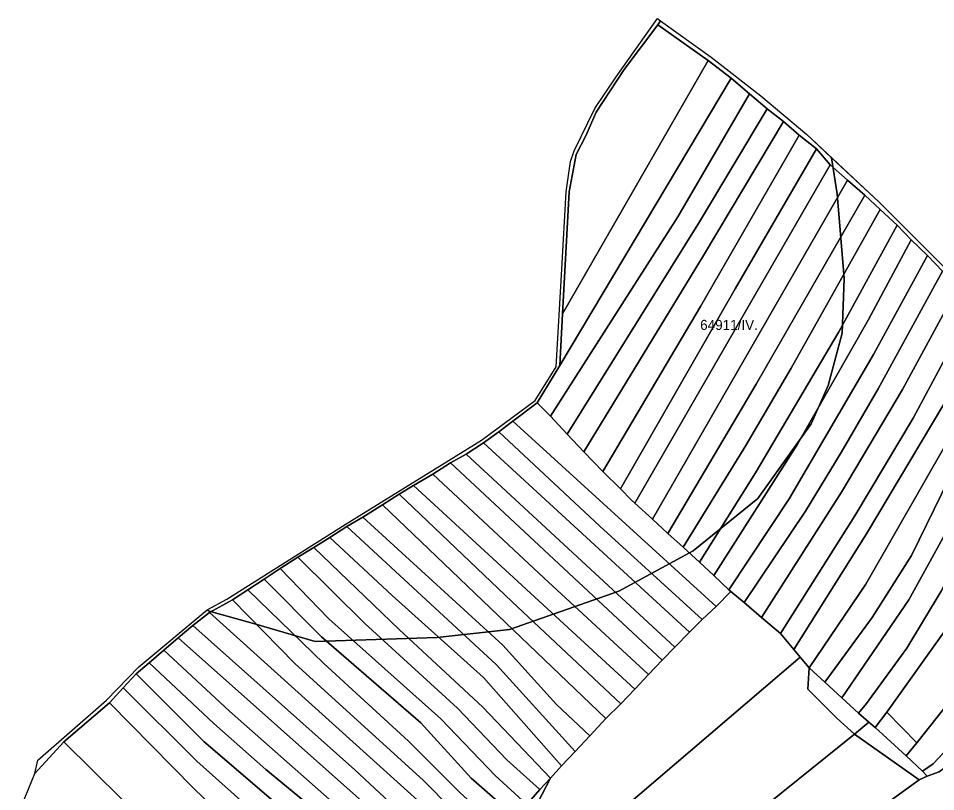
# Model space of a CAD drawing. Extents: x -521261 to -517465, y -1182764 to -1179456.
# Drawn here: x -519678.3 to -519223.1, y -1179839.4 to -1179455.9 of the extents above; entities that cross this region are included whole.
import ezdxf

# ---------------------------------------------------------------- set-up
doc = ezdxf.new("R2010")
doc.units = 0
for name, color, linetype in [('95560013', 7, 'Continuous'), ('95610013', 7, 'Continuous'), ('95620013', 7, 'Continuous'), ('95640013', 7, 'Continuous'), ('95660013', 7, 'Continuous')]:
    doc.layers.add(name, color=color, linetype=linetype)

msp = doc.modelspace()

# ---------------------------------------------------------------- linework, layer by layer
at = {"layer": '95560013'}
for points in [[(-519361.03, -1179459.21), (-519335.99, -1179476.93), (-519408.24, -1179602.42), (-519404.91, -1179542.03), (-519401.48, -1179523.46), (-519396.76, -1179514.25), (-519391.52, -1179502.49), (-519377.6, -1179481.27)], [(-519335.99, -1179476.93), (-519324.66, -1179485.69), (-519409.54, -1179628.05), (-519408.24, -1179602.42)], [(-519324.66, -1179485.69), (-519315.41, -1179493.46), (-519351.01, -1179554.42), (-519414.24, -1179653.26), (-519420.84, -1179646.66), (-519409.54, -1179628.05)], [(-519315.41, -1179493.46), (-519306.64, -1179500.75), (-519340.21, -1179556.81), (-519405.88, -1179662.23), (-519414.24, -1179653.26), (-519351.01, -1179554.42)], [(-519306.64, -1179500.75), (-519298.66, -1179507.18), (-519338.3, -1179573.5), (-519397.74, -1179670.84), (-519405.88, -1179662.23), (-519340.21, -1179556.81)], [(-519298.66, -1179507.18), (-519290.83, -1179513.92), (-519339.86, -1179598.77), (-519388.2, -1179680.61), (-519397.74, -1179670.84), (-519338.3, -1179573.5)], [(-519290.83, -1179513.92), (-519282.3, -1179520.6), (-519322.59, -1179590.16), (-519379.43, -1179689.33), (-519388.2, -1179680.61), (-519339.86, -1179598.77)], [(-519282.3, -1179520.6), (-519275.39, -1179528.63), (-519372.33, -1179696.43), (-519374.03, -1179694.94), (-519379.43, -1179689.33), (-519322.59, -1179590.16)], [(-519275.39, -1179528.63), (-519266.89, -1179536.14), (-519318.19, -1179625.29), (-519363.61, -1179704.38), (-519372.33, -1179696.43)], [(-519266.89, -1179536.14), (-519258.26, -1179543.63), (-519312.18, -1179637.33), (-519356.03, -1179711.44), (-519363.61, -1179704.38), (-519318.19, -1179625.29)], [(-519258.26, -1179543.63), (-519250.63, -1179550.72), (-519294.75, -1179629.37), (-519317.27, -1179667.84), (-519348.37, -1179718.13), (-519356.03, -1179711.44), (-519312.18, -1179637.33)], [(-519250.63, -1179550.72), (-519242.26, -1179558.54), (-519271.17, -1179611.41), (-519312.48, -1179681.33), (-519340.31, -1179725.57), (-519348.37, -1179718.13), (-519317.27, -1179667.84), (-519294.75, -1179629.37)], [(-519242.26, -1179558.54), (-519235.24, -1179565.85), (-519256.56, -1179605.64), (-519291.61, -1179667.15), (-519333.12, -1179732.17), (-519340.31, -1179725.57), (-519312.48, -1179681.33), (-519271.17, -1179611.41)], [(-519235.24, -1179565.85), (-519227.21, -1179573.63), (-519253.98, -1179622.58), (-519295.83, -1179694.23), (-519325.66, -1179739.27), (-519333.12, -1179732.17), (-519291.61, -1179667.15), (-519256.56, -1179605.64)], [(-519227.21, -1179573.63), (-519219.73, -1179581.26), (-519251.57, -1179639.65), (-519270, -1179671.32), (-519287.7, -1179700.28), (-519318.17, -1179745.69), (-519324.74, -1179740.24), (-519325.66, -1179739.27), (-519295.83, -1179694.23), (-519253.98, -1179622.58)], [(-519219.73, -1179581.26), (-519212.15, -1179589.49), (-519239.59, -1179639.98), (-519269.79, -1179690.95), (-519309.58, -1179753.02), (-519318.17, -1179745.69), (-519287.7, -1179700.28), (-519270, -1179671.32), (-519251.57, -1179639.65)], [(-519212.15, -1179589.49), (-519204.52, -1179598.75), (-519234.32, -1179654.26), (-519263.2, -1179702.59), (-519300.17, -1179761.03), (-519309.58, -1179753.02), (-519269.79, -1179690.95), (-519239.59, -1179639.98)], [(-519201.94, -1179601.66), (-519198.05, -1179606.76), (-519219.06, -1179647.31), (-519257.37, -1179711.63), (-519293.42, -1179768.94), (-519300.17, -1179761.03), (-519263.2, -1179702.59), (-519234.32, -1179654.26), (-519204.52, -1179598.75)], [(-519198.05, -1179606.76), (-519192.16, -1179610.6), (-519218.52, -1179663.34), (-519216.58, -1179664.63), (-519257.8, -1179736.51), (-519285.96, -1179778.08), (-519290.27, -1179772.81), (-519293.42, -1179768.94), (-519257.37, -1179711.63), (-519219.06, -1179647.31)], [(-519414.24, -1179653.26), (-519405.88, -1179662.23), (-519397.74, -1179670.84), (-519388.2, -1179680.61), (-519379.43, -1179689.33), (-519374.03, -1179694.94), (-519372.33, -1179696.43), (-519363.61, -1179704.38), (-519356.03, -1179711.44), (-519348.37, -1179718.13), (-519340.31, -1179725.57), (-519333.12, -1179732.17), (-519325.66, -1179739.27), (-519324.74, -1179740.24), (-519331.97, -1179747.61), (-519432.94, -1179655.75), (-519420.84, -1179646.66)], [(-519439.84, -1179660.98), (-519432.94, -1179655.75), (-519331.97, -1179747.61), (-519338.93, -1179754.09), (-519389.67, -1179707.71)], [(-519447.42, -1179666.48), (-519439.84, -1179660.98), (-519389.67, -1179707.71), (-519338.93, -1179754.09), (-519345.21, -1179760.33)], [(-519208.94, -1179668.99), (-519235.04, -1179722.32), (-519254.59, -1179753.09), (-519278.09, -1179785.19), (-519285.96, -1179778.08), (-519257.8, -1179736.51), (-519216.58, -1179664.63)], [(-519456.09, -1179672.01), (-519447.42, -1179666.48), (-519345.21, -1179760.33), (-519352.56, -1179767.71)], [(-519200.9, -1179673.95), (-519219.5, -1179713.79), (-519236.39, -1179744.27), (-519269.7, -1179792.92), (-519278.09, -1179785.19), (-519254.59, -1179753.09), (-519235.04, -1179722.32), (-519208.94, -1179668.99)], [(-519463.87, -1179676.33), (-519456.09, -1179672.01), (-519352.56, -1179767.71), (-519358.76, -1179774.28)], [(-519192.45, -1179678.83), (-519208.08, -1179716.23), (-519220.4, -1179740.02), (-519237.39, -1179768.34), (-519257.44, -1179795.7), (-519261.34, -1179800.45), (-519269.7, -1179792.92), (-519236.39, -1179744.27), (-519219.5, -1179713.79), (-519200.9, -1179673.95)], [(-519472.58, -1179681.98), (-519463.87, -1179676.33), (-519358.76, -1179774.28), (-519365.58, -1179781.36), (-519417.45, -1179733.41)], [(-519482.18, -1179687.66), (-519472.58, -1179681.98), (-519417.45, -1179733.41), (-519365.58, -1179781.36), (-519372.32, -1179788.53)], [(-519489.37, -1179691.96), (-519482.18, -1179687.66), (-519372.32, -1179788.53), (-519379.3, -1179795.8), (-519433.17, -1179745.31)], [(-519497.64, -1179697.24), (-519489.37, -1179691.96), (-519433.17, -1179745.31), (-519379.3, -1179795.8), (-519386.79, -1179803.12)], [(-519507.31, -1179703.34), (-519497.64, -1179697.24), (-519386.79, -1179803.12), (-519394.73, -1179811.81), (-519411.23, -1179796.2), (-519437.91, -1179766.86)], [(-519515.2, -1179707.94), (-519507.31, -1179703.34), (-519437.91, -1179766.86), (-519411.23, -1179796.2), (-519394.73, -1179811.81), (-519401.97, -1179819.49), (-519441.01, -1179776.5)], [(-519523.71, -1179713.36), (-519515.2, -1179707.94), (-519441.01, -1179776.5), (-519401.97, -1179819.49), (-519408.69, -1179826.66), (-519447.53, -1179782.85), (-519492.73, -1179742.1)], [(-519531.57, -1179718.35), (-519523.71, -1179713.36), (-519492.73, -1179742.1), (-519447.53, -1179782.85), (-519408.69, -1179826.66), (-519414.29, -1179832.69), (-519447.72, -1179797.47), (-519489.38, -1179758.96)], [(-519539.55, -1179723.19), (-519531.57, -1179718.35), (-519489.38, -1179758.96), (-519447.72, -1179797.47), (-519414.29, -1179832.69), (-519419.43, -1179838.35), (-519435.84, -1179823.64), (-519460.43, -1179797.99), (-519506.36, -1179756.12)], [(-519548.4, -1179728.82), (-519539.55, -1179723.19), (-519506.36, -1179756.12), (-519460.43, -1179797.99), (-519435.84, -1179823.64), (-519419.43, -1179838.35), (-519423.83, -1179843.37), (-519425.9, -1179845.77), (-519441.61, -1179831.42), (-519468.61, -1179803.29), (-519524.14, -1179753.78)], [(-519556.27, -1179734.13), (-519548.4, -1179728.82), (-519524.14, -1179753.78), (-519468.61, -1179803.29), (-519441.61, -1179831.42), (-519425.9, -1179845.77), (-519431.26, -1179852.28), (-519453.56, -1179832.73), (-519478.58, -1179805.33), (-519527.89, -1179762.65)], [(-519564.43, -1179739.4), (-519556.27, -1179734.13), (-519527.89, -1179762.65), (-519478.58, -1179805.33), (-519453.56, -1179832.73), (-519431.26, -1179852.28), (-519437.26, -1179859.88), (-519459.17, -1179839.89), (-519484.71, -1179814.34), (-519526.65, -1179775.84)], [(-519572.01, -1179744.28), (-519564.43, -1179739.4), (-519526.65, -1179775.84), (-519484.71, -1179814.34), (-519459.17, -1179839.89), (-519437.26, -1179859.88), (-519442.74, -1179866.13), (-519463.3, -1179847.89), (-519477.15, -1179833.93), (-519541.13, -1179775.85)], [(-519324.74, -1179740.24), (-519318.17, -1179745.69), (-519309.58, -1179753.02), (-519300.17, -1179761.03), (-519293.42, -1179768.94), (-519290.27, -1179772.81), (-519405.1, -1179870.79), (-519441.45, -1179905.77), (-519434.67, -1179872.01), (-519414.29, -1179832.69), (-519408.69, -1179826.66), (-519401.97, -1179819.49), (-519394.73, -1179811.81), (-519386.79, -1179803.12), (-519379.3, -1179795.8), (-519372.32, -1179788.53), (-519365.58, -1179781.36), (-519358.76, -1179774.28), (-519352.56, -1179767.71), (-519345.21, -1179760.33), (-519338.93, -1179754.09), (-519331.97, -1179747.61)], [(-519583.34, -1179750.61), (-519572.01, -1179744.28), (-519541.13, -1179775.85), (-519477.15, -1179833.93), (-519463.3, -1179847.89), (-519442.74, -1179866.13), (-519447.98, -1179872.79)], [(-519591.65, -1179757.1), (-519583.34, -1179750.61), (-519447.98, -1179872.79), (-519453.81, -1179880.12), (-519477.04, -1179860.53), (-519511.27, -1179828.64)], [(-519598.98, -1179763.08), (-519591.65, -1179757.1), (-519511.27, -1179828.64), (-519477.04, -1179860.53), (-519453.81, -1179880.12), (-519459.24, -1179886.88), (-519484.38, -1179866.3), (-519500.43, -1179850.73)], [(-519606.08, -1179769.24), (-519598.98, -1179763.08), (-519500.43, -1179850.73), (-519484.38, -1179866.3), (-519497.57, -1179856.71), (-519505.44, -1179859.57), (-519573.52, -1179799.52)], [(-519613.36, -1179775.48), (-519606.08, -1179769.24), (-519573.52, -1179799.52), (-519505.44, -1179859.57), (-519514.27, -1179862.4), (-519555.48, -1179828.46), (-519581.24, -1179805.68)], [(-519285.96, -1179778.08), (-519286.57, -1179788.67), (-519272.15, -1179802.97), (-519263.31, -1179810.97), (-519326.89, -1179861.96), (-519363.99, -1179882.48), (-519414.1, -1179916.88), (-519430.25, -1179928.79), (-519462.01, -1179956.85), (-519460.01, -1179944.72), (-519441.45, -1179905.77), (-519405.1, -1179870.79), (-519290.27, -1179772.81)], [(-519619.83, -1179780.93), (-519613.36, -1179775.48), (-519581.24, -1179805.68), (-519555.48, -1179828.46), (-519514.27, -1179862.4), (-519521.66, -1179869.8), (-519586.19, -1179814.48)], [(-519626.2, -1179787.91), (-519619.83, -1179780.93), (-519586.19, -1179814.48), (-519521.66, -1179869.8), (-519527.72, -1179876.1), (-519556.92, -1179853.62), (-519589.63, -1179824.32)], [(-519414.29, -1179832.69), (-519434.67, -1179872.01), (-519441.45, -1179905.77), (-519444.29, -1179902.47), (-519437.85, -1179871.23), (-519423.83, -1179843.37), (-519419.43, -1179838.35)]]:
    msp.add_lwpolyline(points, close=True, dxfattribs=at)
msp.add_lwpolyline([(-519219.73, -1179581.26), (-519227.21, -1179573.63), (-519235.24, -1179565.85), (-519242.26, -1179558.54), (-519250.63, -1179550.72), (-519258.26, -1179543.63), (-519266.89, -1179536.14), (-519275.39, -1179528.63), (-519282.3, -1179520.6), (-519290.83, -1179513.92), (-519298.66, -1179507.18), (-519306.64, -1179500.75), (-519315.41, -1179493.46), (-519324.66, -1179485.69), (-519335.99, -1179476.93), (-519361.03, -1179459.21), (-519359.72, -1179457.23), (-519334.45, -1179475.21), (-519309.94, -1179494.33), (-519287, -1179513.62), (-519251.17, -1179547.13), (-519199.84, -1179598.31)], dxfattribs=at)
at = {"layer": '95610013'}
for points in [[(-519633.09, -1179795.38), (-519626.2, -1179787.91), (-519589.63, -1179824.32), (-519556.92, -1179853.62), (-519527.72, -1179876.1), (-519514.11, -1179885.13), (-519521.99, -1179890.73), (-519547.23, -1179875.75), (-519573.18, -1179855.2), (-519591.12, -1179837.94)], [(-519655.65, -1179814.79), (-519633.09, -1179795.38), (-519591.12, -1179837.94), (-519573.18, -1179855.2), (-519547.23, -1179875.75), (-519521.99, -1179890.73), (-519523.27, -1179891.82), (-519546.18, -1179886.94), (-519566.55, -1179897.34), (-519612.14, -1179857.75)], [(-519670.03, -1179830.37), (-519655.65, -1179814.79), (-519612.14, -1179857.75), (-519566.55, -1179897.34), (-519570.09, -1179903.01), (-519587.53, -1179930.32), (-519606.04, -1179915.21), (-519629.1, -1179889.8), (-519635.04, -1179884.43), (-519678.25, -1179850.34)]]:
    msp.add_lwpolyline(points, close=True, dxfattribs=at)
at = {"layer": '95620013'}
for points in [[(-519165.33, -1179642.89), (-519203.08, -1179731.93), (-519218.13, -1179759.01), (-519247.38, -1179800.01), (-519253.19, -1179807.65), (-519256.33, -1179804.92), (-519261.34, -1179800.45), (-519257.44, -1179795.7), (-519237.39, -1179768.34), (-519220.4, -1179740.02), (-519208.08, -1179716.23), (-519192.45, -1179678.83), (-519174.76, -1179636.77)], [(-519150.46, -1179652.92), (-519159.5, -1179682.18), (-519183.71, -1179745.23), (-519206.07, -1179781.78), (-519232.52, -1179815.22), (-519247.38, -1179800.01), (-519218.13, -1179759.01), (-519203.08, -1179731.93), (-519165.33, -1179642.89)], [(-519138.3, -1179659.87), (-519146.26, -1179687.9), (-519171.64, -1179753.42), (-519187.03, -1179781.08), (-519203.69, -1179803.66), (-519224.32, -1179825.65), (-519229.57, -1179829.19), (-519237.73, -1179821.74), (-519232.52, -1179815.22), (-519206.07, -1179781.78), (-519183.71, -1179745.23), (-519159.5, -1179682.18), (-519150.46, -1179652.92)], [(-519120.9, -1179672.9), (-519151.04, -1179742.19), (-519160.34, -1179760.25), (-519172.06, -1179783.41), (-519178.49, -1179791.88), (-519188.78, -1179803.13), (-519194.43, -1179808.87), (-519205.71, -1179818.1), (-519221.39, -1179829.57), (-519227.27, -1179831.72), (-519229.57, -1179829.19), (-519224.32, -1179825.65), (-519203.69, -1179803.66), (-519187.03, -1179781.08), (-519171.64, -1179753.42), (-519146.26, -1179687.9), (-519138.3, -1179659.87)], [(-519278.09, -1179785.19), (-519269.7, -1179792.92), (-519261.34, -1179800.45), (-519256.33, -1179804.92), (-519263.31, -1179810.97), (-519272.15, -1179802.97), (-519286.57, -1179788.67), (-519285.96, -1179778.08)], [(-519253.19, -1179807.65), (-519247.38, -1179800.01), (-519232.52, -1179815.22), (-519237.73, -1179821.74)], [(-519256.33, -1179804.92), (-519253.19, -1179807.65), (-519237.73, -1179821.74), (-519229.57, -1179829.19), (-519227.27, -1179831.72), (-519231.25, -1179833.5), (-519263.31, -1179810.97)], [(-519205.71, -1179818.1), (-519194.43, -1179808.87), (-519165.09, -1179835.93), (-519192.84, -1179864.25), (-519199.62, -1179870.4), (-519238.71, -1179905.52), (-519269.76, -1179928.77), (-519275.76, -1179931.8), (-519291.7, -1179939.47), (-519307.71, -1179957.39), (-519334.26, -1179925.13), (-519326.04, -1179909.41), (-519317.27, -1179895.86), (-519310.04, -1179890.61), (-519231.25, -1179833.5), (-519227.27, -1179831.72), (-519221.39, -1179829.57)], [(-519231.25, -1179833.5), (-519310.04, -1179890.61), (-519317.27, -1179895.86), (-519326.04, -1179909.41), (-519334.26, -1179925.13), (-519363.99, -1179882.48), (-519326.89, -1179861.96), (-519263.31, -1179810.97)]]:
    msp.add_lwpolyline(points, close=True, dxfattribs=at)
at = {"layer": '95640013'}
msp.add_lwpolyline([(-519359.72, -1179457.23), (-519361.03, -1179459.21), (-519377.6, -1179481.27), (-519391.52, -1179502.49), (-519396.76, -1179514.25), (-519401.48, -1179523.46), (-519404.91, -1179542.03), (-519408.24, -1179602.42), (-519409.54, -1179628.05), (-519420.84, -1179646.66), (-519432.94, -1179655.75), (-519439.84, -1179660.98), (-519447.42, -1179666.48), (-519456.09, -1179672.01), (-519463.87, -1179676.33), (-519472.58, -1179681.98), (-519482.18, -1179687.66), (-519489.37, -1179691.96), (-519497.64, -1179697.24), (-519507.31, -1179703.34), (-519515.2, -1179707.94), (-519523.71, -1179713.36), (-519531.57, -1179718.35), (-519539.55, -1179723.19), (-519548.4, -1179728.82), (-519556.27, -1179734.13), (-519564.43, -1179739.4), (-519572.01, -1179744.28), (-519583.34, -1179750.61), (-519591.65, -1179757.1), (-519598.98, -1179763.08), (-519606.08, -1179769.24), (-519613.36, -1179775.48), (-519619.83, -1179780.93), (-519626.2, -1179787.91), (-519633.09, -1179795.38), (-519655.65, -1179814.79), (-519670.03, -1179830.37), (-519668.57, -1179823.87), (-519634.54, -1179794.1), (-519618.53, -1179777.52), (-519584.53, -1179749.32), (-519574.82, -1179743.99), (-519516.1, -1179706.88), (-519448.52, -1179665.15), (-519421.79, -1179645.43), (-519411.44, -1179628.84), (-519408.63, -1179580.37), (-519406.46, -1179542.05), (-519404.28, -1179526.89), (-519402.45, -1179521.61), (-519392.24, -1179500.69), (-519381.57, -1179484.98), (-519361.21, -1179455.95)], close=True, dxfattribs=at)
at = {"layer": '95660013'}
msp.add_lwpolyline([(-519583.5, -1179750), (-519584.55, -1179749.34), (-519584.53, -1179749.32), (-519574.82, -1179743.99), (-519516.1, -1179706.88), (-519448.52, -1179665.15), (-519421.79, -1179645.43), (-519411.44, -1179628.84), (-519408.63, -1179580.37), (-519406.46, -1179542.05), (-519404.28, -1179526.89), (-519402.45, -1179521.61), (-519392.24, -1179500.69), (-519381.57, -1179484.98), (-519361.21, -1179455.95), (-519359.72, -1179457.23), (-519334.45, -1179475.21), (-519309.94, -1179494.33), (-519287, -1179513.62), (-519274.74, -1179525.09), (-519272, -1179543), (-519268.59, -1179585), (-519269.59, -1179612), (-519276.41, -1179638), (-519284.91, -1179657), (-519311.41, -1179694), (-519343.5, -1179720), (-519380.31, -1179740), (-519434.5, -1179759), (-519470.5, -1179763), (-519531, -1179765), (-519561.5, -1179756)], close=True, dxfattribs=at)
for points in [[(-519678.25, -1179850.34), (-519670.03, -1179830.37), (-519668.57, -1179823.87), (-519634.54, -1179794.1), (-519618.53, -1179777.52), (-519584.55, -1179749.34), (-519583.5, -1179750), (-519561.5, -1179756), (-519531, -1179765), (-519470.5, -1179763), (-519434.5, -1179759), (-519380.31, -1179740), (-519343.5, -1179720), (-519311.41, -1179694), (-519284.91, -1179657), (-519276.41, -1179638), (-519269.59, -1179612), (-519268.59, -1179585), (-519272, -1179543), (-519274.74, -1179525.09), (-519251.17, -1179547.13), (-519199.84, -1179598.31)], [(-519326.89, -1179861.96), (-519263.31, -1179810.97), (-519272.15, -1179802.97), (-519286.57, -1179788.67), (-519285.96, -1179778.08), (-519278.09, -1179785.19), (-519269.7, -1179792.92), (-519261.34, -1179800.45), (-519257.44, -1179795.7), (-519237.39, -1179768.34), (-519220.4, -1179740.02)], [(-519220.4, -1179740.02), (-519237.39, -1179768.34), (-519257.44, -1179795.7), (-519261.34, -1179800.45), (-519269.7, -1179792.92), (-519278.09, -1179785.19), (-519285.96, -1179778.08), (-519286.57, -1179788.67), (-519272.15, -1179802.97), (-519263.31, -1179810.97), (-519326.89, -1179861.96)]]:
    msp.add_lwpolyline(points, dxfattribs=at)

# ---------------------------------------------------------------- texts
msp.add_text('64911/IV.', height=5, rotation=0, dxfattribs=at).set_placement((-519339.96, -1179610.47))

doc.saveas('drawing.dxf')
